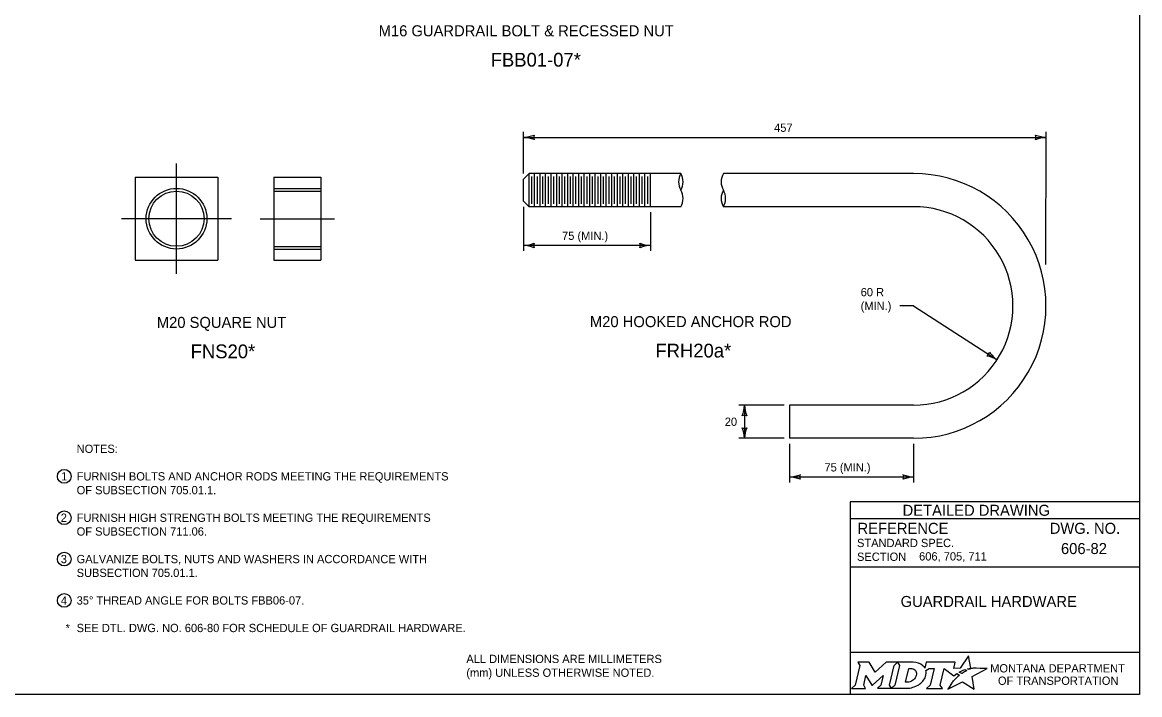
# Model space of a CAD drawing. Extents: x 49991.4 to 50021, y 49987.6 to 50011.4.
# Drawn here: x 50008.65 to 50016.75, y 49987.8 to 49992.68 of the extents above; entities that cross this region are included whole.
import ezdxf

# ---------------------------------------------------------------- set-up
doc = ezdxf.new("R2010")
doc.units = 0
for name, color, linetype in [('Default', 7, 'Continuous'), ('Level 1', 7, 'Continuous'), ('Level 2', 7, 'Continuous'), ('Level 3', 7, 'Continuous'), ('Level 4', 7, 'Continuous'), ('Level 5', 7, 'Continuous')]:
    doc.layers.add(name, color=color, linetype=linetype)

msp = doc.modelspace()

# ---------------------------------------------------------------- linework, layer by layer
at = {"layer": 'Default'}
for points in [[(50015.5126, 49987.9811), (50015.5023, 49987.9867), (50015.5139, 49987.9895), (50015.5255, 49987.9915), (50015.5081, 49988.0816), (50015.4486, 49987.9903), (50015.4013, 49987.9896), (50015.4116, 49988.0337), (50015.2024, 49988.0338), (50015.1923, 49987.9913), (50015.1865, 49987.9996)], [(50014.7056, 49988.0338), (50014.7197, 49988.0104), (50014.6862, 49987.8671), (50014.6605, 49987.8446), (50014.7621, 49987.8446), (50014.7486, 49987.8674), (50014.7648, 49987.9375), (50014.8085, 49987.8685), (50014.8138, 49987.8685), (50014.8889, 49987.938), (50014.8725, 49987.8669), (50014.8478, 49987.8449), (50014.9494, 49987.8449), (50014.9356, 49987.8682), (50014.9688, 49988.0106)], [(50014.9688, 49988.0106), (50014.9941, 49988.0338), (50014.9117, 49988.0338), (50014.8321, 49987.9608), (50014.7876, 49988.0335), (50014.7056, 49988.0338)], [(50015.1077, 49988.0338), (50014.9941, 49988.0338), (50015.0088, 49988.0109), (50014.9749, 49987.8671), (50014.9494, 49987.8449), (50015.06, 49987.8449)], [(50015.1317, 49987.9471), (50015.1305, 49987.939), (50015.1273, 49987.9297), (50015.1231, 49987.9215), (50015.1175, 49987.914), (50015.111, 49987.9071), (50015.1031, 49987.9008), (50015.0948, 49987.8961), (50015.0857, 49987.8922), (50015.0766, 49987.8899), (50015.0674, 49987.889), (50015.0515, 49987.889), (50015.0751, 49987.989), (50015.0911, 49987.989), (50015.0987, 49987.9884), (50015.1063, 49987.9865), (50015.1129, 49987.9835), (50015.119, 49987.9793), (50015.1238, 49987.9743), (50015.1275, 49987.9683), (50015.1302, 49987.9621), (50015.1318, 49987.9547), (50015.1318, 49987.9517), (50015.1317, 49987.9471)], [(50015.1991, 49987.9747), (50015.2237, 49987.9878), (50015.2606, 49987.9878), (50015.232, 49987.8673), (50015.2045, 49987.8446), (50015.3207, 49987.8446), (50015.3037, 49987.8675), (50015.3319, 49987.9877), (50015.4032, 49987.936), (50015.4243, 49987.9511), (50015.444, 49987.9402)], [(50015.3882, 49987.8843), (50015.3729, 49987.8599), (50015.3682, 49987.8524), (50015.3624, 49987.8438), (50015.3601, 49987.8395), (50015.4654, 49987.8926), (50015.5493, 49987.8375), (50015.5362, 49987.9302), (50015.6431, 49987.9886), (50015.5938, 49987.9894), (50015.5637, 49987.9898), (50015.5429, 49987.9901), (50015.5361, 49987.9886), (50015.5312, 49987.9874), (50015.5228, 49987.9851), (50015.5126, 49987.9811)], [(50015.4622, 49987.9535), (50015.4598, 49987.9518), (50015.4415, 49987.9614), (50015.4518, 49987.9671), (50015.4559, 49987.9693), (50015.4645, 49987.9733), (50015.4702, 49987.9759), (50015.4781, 49987.9789), (50015.4854, 49987.9816), (50015.4972, 49987.9742), (50015.4932, 49987.9721), (50015.4886, 49987.9696), (50015.4844, 49987.9674), (50015.4794, 49987.9645), (50015.4775, 49987.9634), (50015.4748, 49987.9618), (50015.4723, 49987.9604), (50015.47, 49987.9588), (50015.4674, 49987.957), (50015.4647, 49987.9552), (50015.4622, 49987.9535)], [(50015.1057, 49987.8522), (50015.1141, 49987.8548), (50015.1271, 49987.8602), (50015.1475, 49987.8712)], [(50015.4021, 49987.9004), (50015.4021, 49987.9004)]]:
    msp.add_lwpolyline(points, dxfattribs=at)
for centre, radius, start, end in [((50015.0868, 49987.9727), 0.1183, 300.91025, 339.13831), ((50015.1308, 49987.9554), 0.0709, 339.53292, 15.85821)]:
    msp.add_arc(centre, radius, start, end, dxfattribs=at)
for centre, major_axis, ratio, start_param, end_param in [((50015.1056, 49987.9864), (0.0834, -0.0037), 0.568097, 0.61298, 1.570796), ((50015.1612, 49987.9937), (0.0361, -0.0295), 0.469099, 1.225588, 1.570796), ((50015.4119, 49987.9106), (-0.0098, -0.0102), 0.016458, 3.141593, 6.279097), ((50015.4329, 49987.9305), (-0.0112, -0.0097), 0.021651, 3.157348, 6.283185), ((50015.0603, 49987.9932), (0, 0.1484), 0.987302, 3.139398, 3.456847), ((50015.3952, 49987.8923), (-0.00694, -0.00806), 0.008222, 0, 3.137361)]:
    msp.add_ellipse(centre, major_axis=major_axis, ratio=ratio, start_param=start_param, end_param=end_param, dxfattribs=at)
at = {"layer": 'Level 1'}
for p, q in [((50009.4651, 49991.5517), (50010.0651, 49991.5517)), ((50009.4651, 49991.5517), (50009.4651, 49990.9517)), ((50010.0651, 49991.5517), (50010.0651, 49990.9517)), ((50010.472, 49991.5517), (50010.472, 49990.9517)), ((50010.472, 49991.5517), (50010.812, 49991.5517)), ((50010.812, 49991.5517), (50010.812, 49990.9517)), ((50012.2823, 49991.5385), (50012.3223, 49991.5785)), ((50013.4223, 49991.5786), (50012.3223, 49991.5785)), ((50012.3223, 49991.3385), (50012.3223, 49991.5785)), ((50012.3423, 49991.3585), (50012.3423, 49991.5585)), ((50012.3623, 49991.3385), (50012.3623, 49991.5785)), ((50012.3823, 49991.3585), (50012.3823, 49991.5585)), ((50012.4023, 49991.3385), (50012.4023, 49991.5785)), ((50012.4223, 49991.3585), (50012.4223, 49991.5585)), ((50012.4423, 49991.3385), (50012.4423, 49991.5785)), ((50012.4623, 49991.3585), (50012.4623, 49991.5585)), ((50012.4823, 49991.3385), (50012.4823, 49991.5785)), ((50012.5023, 49991.3585), (50012.5023, 49991.5585)), ((50012.5223, 49991.3385), (50012.5223, 49991.5785)), ((50012.5423, 49991.3585), (50012.5423, 49991.5585)), ((50012.5623, 49991.3385), (50012.5623, 49991.5785)), ((50012.5823, 49991.3585), (50012.5823, 49991.5585)), ((50012.6023, 49991.3385), (50012.6023, 49991.5785)), ((50012.6223, 49991.3585), (50012.6223, 49991.5585)), ((50012.6423, 49991.3385), (50012.6423, 49991.5785)), ((50012.6623, 49991.3585), (50012.6623, 49991.5585)), ((50012.6823, 49991.3385), (50012.6823, 49991.5785)), ((50012.7023, 49991.3585), (50012.7023, 49991.5585)), ((50012.7223, 49991.3385), (50012.7223, 49991.5785)), ((50012.7423, 49991.3585), (50012.7423, 49991.5585)), ((50012.7623, 49991.3385), (50012.7623, 49991.5785)), ((50012.7823, 49991.3585), (50012.7823, 49991.5585)), ((50012.8023, 49991.3385), (50012.8023, 49991.5785)), ((50012.8223, 49991.3585), (50012.8223, 49991.5585)), ((50012.8423, 49991.3385), (50012.8423, 49991.5785)), ((50012.8623, 49991.3585), (50012.8623, 49991.5585)), ((50012.8823, 49991.3385), (50012.8823, 49991.5785)), ((50012.9023, 49991.3585), (50012.9023, 49991.5585)), ((50012.9223, 49991.3385), (50012.9223, 49991.5785)), ((50012.9423, 49991.3585), (50012.9423, 49991.5585)), ((50012.9623, 49991.3386), (50012.9623, 49991.5786)), ((50012.9823, 49991.3585), (50012.9823, 49991.5585)), ((50013.0023, 49991.3386), (50013.0023, 49991.5786)), ((50013.0223, 49991.3585), (50013.0223, 49991.5585)), ((50013.0423, 49991.3386), (50013.0423, 49991.5786)), ((50013.0623, 49991.3585), (50013.0623, 49991.5585)), ((50013.0823, 49991.3386), (50013.0823, 49991.5786)), ((50013.1023, 49991.3585), (50013.1023, 49991.5585)), ((50013.1223, 49991.3386), (50013.1223, 49991.5786)), ((50013.1423, 49991.3585), (50013.1423, 49991.5585)), ((50013.1623, 49991.3386), (50013.1623, 49991.5786)), ((50013.1823, 49991.3585), (50013.1823, 49991.5585)), ((50013.2023, 49991.3386), (50013.2023, 49991.5786)), ((50015.1109, 49991.5787), (50013.7309, 49991.5786)), ((50012.2823, 49991.3785), (50012.2823, 49991.5385)), ((50012.2823, 49991.3785), (50012.3223, 49991.3385)), ((50013.4223, 49991.3386), (50012.3223, 49991.3385)), ((50015.1109, 49991.3387), (50013.7309, 49991.3386)), ((50009.4651, 49990.9517), (50010.0651, 49990.9517)), ((50010.472, 49990.9517), (50010.812, 49990.9517)), ((50015.1109, 49989.8987), (50014.2109, 49989.8986)), ((50014.2109, 49989.8986), (50014.2109, 49989.6586)), ((50015.1109, 49989.6587), (50014.2109, 49989.6586))]:
    msp.add_line(p, q, dxfattribs=at)
msp.add_lwpolyline([(49999.3835, 49998.9992), (50016.7501, 49998.9992), (50016.7501, 49987.7988), (49999.3835, 49987.7988)], close=True, dxfattribs=at)
msp.add_circle((50009.7651, 49991.2517), 0.2, dxfattribs=at)
for centre, radius, start, end in [((50013.5263, 49991.5186), 0.12, 149.99758, 209.9976), ((50013.3184, 49991.5186), 0.12, 329.99758, 29.9976), ((50013.8348, 49991.5186), 0.12, 149.99759, 209.99759), ((50015.1109, 49990.6187), 0.96, 269.99515, 90.00242), ((50013.3184, 49991.3986), 0.12, 330.00241, 30.00241), ((50013.8348, 49991.3986), 0.12, 150.00241, 210.00241), ((50013.627, 49991.3986), 0.12, 330.00241, 30.00241), ((50015.1109, 49990.6187), 0.72, 269.99391, 90.00242)]:
    msp.add_arc(centre, radius, start, end, dxfattribs=at)
at = {"layer": 'Level 2'}
for centre in [(50008.951, 49989.3825), (50008.951, 49989.0825), (50008.951, 49988.7825), (50008.951, 49988.4825)]:
    msp.add_circle(centre, 0.05, dxfattribs=at)
at = {"layer": 'Level 3'}
for p, q in [((50012.2823, 49991.5785), (50012.2823, 49991.8817)), ((50016.0709, 49990.9187), (50016.071, 49991.8817)), ((50012.2823, 49991.8417), (50016.071, 49991.8417)), ((50012.2823, 49991.3385), (50012.2823, 49991.0178)), ((50013.2023, 49991.2986), (50013.2023, 49991.0178)), ((50013.2023, 49991.0578), (50012.2823, 49991.0578)), ((50015.1109, 49990.6187), (50015.0109, 49990.6187)), ((50015.1109, 49990.6187), (50015.7158, 49990.2281)), ((50014.1709, 49989.8986), (50013.844, 49989.8986)), ((50013.884, 49989.8986), (50013.884, 49989.6586)), ((50014.1709, 49989.6586), (50013.844, 49989.6586)), ((50014.2109, 49989.6186), (50014.2109, 49989.3379)), ((50015.1109, 49989.6187), (50015.1109, 49989.3379)), ((50014.2109, 49989.3779), (50015.1109, 49989.3779))]:
    msp.add_line(p, q, dxfattribs=at)
for centre, radius, start, end in [((50012.2732, 49992.0638), 0.2223, 272.36048, 292.54399), ((50012.2708, 49991.609), 0.233, 67.92284, 87.17269), ((50012.4106, 49991.8417), 0.0548, 162.13882, 197.86118), ((50015.9428, 49991.8417), 0.0548, 342.13882, 17.86118), ((50016.0825, 49992.0744), 0.233, 247.92284, 267.17269), ((50016.0801, 49991.6195), 0.2223, 92.36048, 112.54399), ((50012.2732, 49991.2799), 0.2223, 272.36048, 292.54399), ((50012.4106, 49991.0578), 0.0548, 162.13882, 197.86118), ((50013.0741, 49991.0578), 0.0548, 342.13882, 17.86118), ((50013.2138, 49991.2905), 0.233, 247.92284, 267.17269), ((50012.2708, 49990.8251), 0.233, 67.92284, 87.17269), ((50013.2115, 49990.8357), 0.2223, 92.36048, 112.54399), ((50015.6082, 49990.2979), 0.0548, 309.15424, 344.8766), ((50015.6025, 49990.0368), 0.2223, 59.3759, 79.55941), ((50015.8521, 49990.4171), 0.233, 214.93826, 234.18811), ((50013.6618, 49989.9078), 0.2223, 337.45601, 357.63952), ((50014.1167, 49989.9101), 0.233, 182.82731, 202.07716), ((50013.884, 49989.7704), 0.0548, 72.13882, 107.86118), ((50013.884, 49989.7868), 0.0548, 252.13882, 287.86118), ((50013.6512, 49989.6471), 0.233, 2.82731, 22.07716), ((50014.1061, 49989.6495), 0.2223, 157.45601, 177.63952), ((50014.2017, 49989.6), 0.2223, 272.36048, 292.54399), ((50014.1994, 49989.1452), 0.233, 67.92284, 87.17269), ((50014.3391, 49989.3779), 0.0548, 162.13882, 197.86118), ((50014.9827, 49989.3779), 0.0548, 342.13882, 17.86118), ((50015.1224, 49989.6106), 0.233, 247.92284, 267.17269), ((50015.12, 49989.1558), 0.2223, 92.36048, 112.54399)]:
    msp.add_arc(centre, radius, start, end, dxfattribs=at)
at = {"layer": 'Level 4'}
for p, q in [((50010.472, 49991.4717), (50010.812, 49991.4717)), ((50010.472, 49991.4517), (50010.812, 49991.4517)), ((50010.472, 49991.0505), (50010.812, 49991.0505)), ((50010.472, 49991.0317), (50010.812, 49991.0317))]:
    msp.add_line(p, q, dxfattribs=at)
msp.add_circle((50009.7651, 49991.2517), 0.22, dxfattribs=at)
at = {"layer": 'Level 5'}
for p, q in [((50009.7651, 49990.8517), (50009.7651, 49991.6517)), ((50010.1651, 49991.2517), (50009.3651, 49991.2517)), ((50010.372, 49991.2517), (50010.912, 49991.2517)), ((50016.7501, 49989.1988), (50014.6501, 49989.1988)), ((50014.6501, 49989.1988), (50014.6501, 49987.7988)), ((50016.7501, 49989.0738), (50014.6501, 49989.0738)), ((50015.1444, 49988.7993), (50015.1444, 49988.7993)), ((50016.3862, 49988.8587), (50016.3862, 49988.8587)), ((50016.7501, 49988.7238), (50014.6501, 49988.7238)), ((50015.7001, 49988.4747), (50015.7001, 49988.4747)), ((50016.7501, 49988.1057), (50014.6501, 49988.1057))]:
    msp.add_line(p, q, dxfattribs=at)

# ---------------------------------------------------------------- texts
at = {"layer": 'Default'}
for s, p in [('MONTANA DEPARTMENT', (50015.6663, 49987.96)), ('OF TRANSPORTATION', (50015.7225, 49987.87))]:
    msp.add_text(s, height=0.06, dxfattribs=at).set_placement(p)
at = {"layer": 'Level 2'}
for s, height, p in [('M16 GUARDRAIL BOLT & RECESSED NUT', 0.08, (50011.2312, 49992.5747)), ('FBB01-07*', 0.1, (50012.0437, 49992.3547)), ('457', 0.06, (50014.099, 49991.8817)), ('75 (MIN.)', 0.06, (50012.5613, 49991.0978)), ('60 R', 0.06, (50014.727, 49990.6887)), ('(MIN.)', 0.06, (50014.727, 49990.5887)), ('M20 SQUARE NUT', 0.08, (50009.6222, 49990.4592)), ('M20 HOOKED ANCHOR ROD', 0.08, (50012.7633, 49990.4648)), ('FNS20*', 0.1, (50009.8677, 49990.2392)), ('FRH20a*', 0.1, (50013.2381, 49990.2448)), ('20', 0.06, (50013.7413, 49989.7486)), ('NOTES:', 0.06, (50009.041, 49989.5525)), ('75 (MIN.)', 0.06, (50014.4641, 49989.4179)), ('1', 0.06, (50008.9283, 49989.3525)), ('FURNISH BOLTS AND ANCHOR RODS MEETING THE REQUIREMENTS', 0.06, (50009.041, 49989.3525)), ('OF SUBSECTION 705.01.1.', 0.06, (50009.041, 49989.2525)), ('2', 0.06, (50008.9258, 49989.0525)), ('FURNISH HIGH STRENGTH BOLTS MEETING THE REQUIREMENTS', 0.06, (50009.041, 49989.0525)), ('OF SUBSECTION 711.06.', 0.06, (50009.041, 49988.9525)), ('606-82', 0.08, (50016.1796, 49988.8187)), ('3', 0.06, (50008.9258, 49988.7525)), ('GALVANIZE BOLTS, NUTS AND WASHERS IN ACCORDANCE WITH ', 0.06, (50009.041, 49988.7525)), ('606, 705, 711', 0.06, (50015.1508, 49988.772)), ('SUBSECTION 705.01.1.', 0.06, (50009.041, 49988.6525)), ('4', 0.06, (50008.927, 49988.4525)), ('35° THREAD ANGLE FOR BOLTS FBB06-07.', 0.06, (50009.041, 49988.4525)), ('GUARDRAIL HARDWARE', 0.08, (50015.0167, 49988.4347)), ('*', 0.06, (50008.9612, 49988.2525)), ('SEE DTL. DWG. NO. 606-80 FOR SCHEDULE OF GUARDRAIL HARDWARE.', 0.06, (50009.041, 49988.2525)), ('ALL DIMENSIONS ARE MILLIMETERS', 0.06, (50011.8672, 49988.0282)), ('(mm) UNLESS OTHERWISE NOTED.', 0.06, (50011.8672, 49987.9282))]:
    msp.add_text(s, height=height, dxfattribs=at).set_placement(p)
at = {"layer": 'Level 5'}
for s, height, p in [('DETAILED DRAWING', 0.0799, (50015.0311, 49989.0963)), ('REFERENCE', 0.08, (50014.7037, 49988.9654)), ('DWG. NO.', 0.08, (50016.0979, 49988.9654)), ('STANDARD SPEC.', 0.06, (50014.7004, 49988.8694)), ('SECTION', 0.06, (50014.7004, 49988.7694))]:
    msp.add_text(s, height=height, dxfattribs=at).set_placement(p)

doc.saveas('drawing.dxf')
